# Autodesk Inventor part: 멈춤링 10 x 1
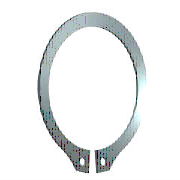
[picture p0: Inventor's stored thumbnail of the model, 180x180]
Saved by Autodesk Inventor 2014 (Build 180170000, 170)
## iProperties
IsCustomPart: 0
Created: 2015-11
Part Number: 멈춤링 10 x 1
Material: 스테인리스강
Description: 리테이닝 링(C형)
Document SubType Name: Modeling
Standard: KS B 1336
Designer: mdu
Standards Organization: KS
Language: ko-KR
Size Designation: 10 x 1
Categories: <MemberInstance><Categories><Category DisplayName="샤프트 부품" InternalName="7f7aeb1f-a693-4053-b835-cee3144e0d98" Mnemonic="SHFT"><Category DisplayName="써클립" Inter
Density: 8.08 g/cm^3
Appearance: 반광택
Mass: 0.434929 g
Surface Area: 1.9243 cm^2
Volume: 0.0538279 cm^3
Author: mdu
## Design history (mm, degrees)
sketch "스케치1"
  geometry: L1 (-6, 0)-(6, 0) reference; L2 (0, 20.189)-(0, -80.536) reference; L3 (-48.09, 0)-(48.09, 0) reference; L4 (-0.3, -9.791)-(-0.3, -12.791); L5 (-0.3, -6.54)-(-0.3, -13.29); L6 (-2.795, 1.6)-(3.672, 1.6); L7 (0.3, -6.54)-(0.3, -13.29); L8 (0.3, -9.791)-(0.3, -12.791); C1 r 0.6 at (-1.2, -11.486); C2 r 0.6 at (1.2, -11.486); A1 r 4.8 centre (0, -5) between (0.3, -9.791) and (-0.3, -9.791); A2 r 6.2 centre (0, -4.6) between (2.988, -10.033) and (-2.988, -10.033); A3 r 7.796 centre (0, -5) between (-1.418, -12.666) and (-0.3, -12.791); A4 r 1.2 centre (-1.2, -11.486) between (-2.383, -11.285) and (-1.418, -12.666); A5 r 1.2 centre (-3.566, -11.084) between (-2.383, -11.285) and (-2.988, -10.033); A6 r 1.2 centre (3.566, -11.084) between (2.988, -10.033) and (2.383, -11.285); A7 r 1.2 centre (1.2, -11.486) between (1.418, -12.666) and (2.383, -11.285); A8 r 7.796 centre (0, -5) between (0.3, -12.791) and (1.418, -12.666)
  constraints: 16 point on circle, 12 end point, 10 centre point, 9 symmetric about line, 5 point on line, 4 tangent, 3 coincident, 2 horizontal, 1 perpendicular, 1 vertical, 5 other
  dimensions: "d0" = 9.6 diameter of A1 (= ND); "d1" = 3 distance of L4.end L4.start (= SRB2); "d6" = 0.3 distance between parallel lines of L2 L5 (= 0.25 x SD5); "d7" = 1.6 distance between parallel lines of L6 L3 (= SRB1); "d8" = 0.4 distance of A1.centre A2.centre (= 0.25 x SRB1); "d9" = 1.2 radius of A4 (= SD5); "d10" = 1.2 radius of A5 (= SD5); "d11" = 0.9 distance from line of L4 A4.centre (= 0.75 x SD5); "d12" = 1.2 diameter of C1 (= SD5); "d13" = 1.2 diameter of C2 (= SD5); "d14" = 5 distance from line of A1.centre L1 (= 0.5 x WD)
extrude "본체" new body sketch "스케치1" distance "d2" = 1 (= SD); taper "d3" = 0 deg
workaxis "Work Axis1"
workplane "Work Plane1"
body "Solid1"
other parameters: "SD" = 1 [user parameter; used in 1 equation term], "SRB1" = 1.6 [user parameter; used in 2 equation terms], "ND" = 9.6 [user parameter; used in 1 equation term], "SRB2" = 3 [user parameter; used in 1 equation term], "SD5" = 1.2 [user parameter; used in 6 equation terms], "d15" = 0, "d16" = 0, "d17" = 0, "d41" = 0, "d42" = 0, "SD3" = 9.3 [user parameter], "WDMAX" = 11 [user parameter]
